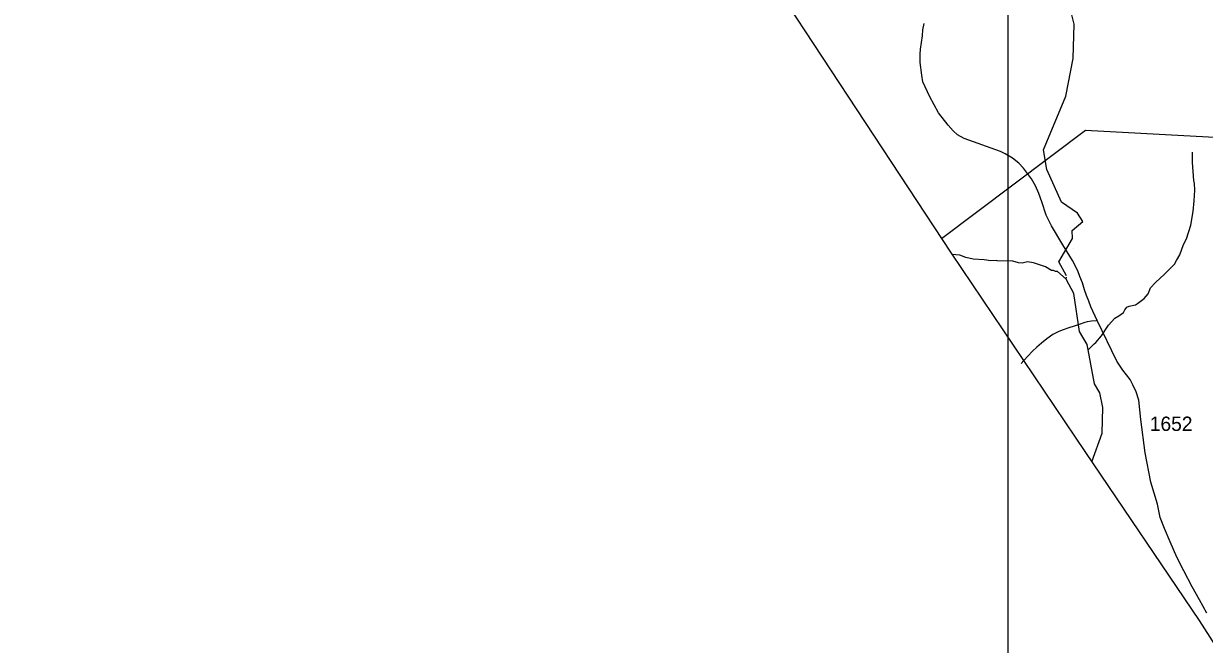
# Model space of a CAD drawing. Extents: x 1268485 to 1426702, y 514839 to 616766.
# Drawn here: x 1268485 to 1280633, y 598258 to 604649 of the extents above; entities that cross this region are included whole.
import ezdxf

# ---------------------------------------------------------------- set-up
doc = ezdxf.new("R2010")
doc.units = 0
for name, color, linetype in [('Old_Level_31', 7, 'Continuous'), ('Old_Level_32', 7, 'Continuous'), ('Old_Level_35', 7, 'Continuous'), ('Old_Level_50', 7, 'Continuous'), ('Old_Level_52', 7, 'Continuous'), ('Old_Level_59', 7, 'Continuous'), ('Old_Level_62', 7, 'Continuous'), ('Old_Level_63', 7, 'Continuous'), ('Old_Level_8', 7, 'Continuous')]:
    doc.layers.add(name, color=color, linetype=linetype)

msp = doc.modelspace()

# ---------------------------------------------------------------- linework, layer by layer
at = {"layer": 'Old_Level_31'}
msp.add_line((1279281.399, 602330.038), (1279281.399, 602330.038), dxfattribs=at)
at = {"layer": 'Old_Level_32'}
msp.add_lwpolyline([(1280657.263, 598578.305), (1280582.342, 598717.072), (1280506.059, 598850.551), (1280420.241, 599017.072), (1280349.406, 599154.517), (1280279.934, 599313.107), (1280221.359, 599450.553), (1280179.131, 599565.53), (1280149.163, 599702.975), (1280083.528, 599927.606), (1280024.873, 600230.577), (1279977.589, 600574.264), (1279959.817, 600773.459), (1279932.574, 600859.362), (1279898.518, 600930.729), (1279868.55, 600986.235), (1279793.629, 601080.067), (1279731, 601174.459), (1279529.362, 601592.843), (1279465.339, 601734.252), (1279443.544, 601792.403), (1279421.749, 601849.231), (1279401.316, 601908.702), (1279378.159, 601981.389), (1279350.915, 602046.147), (1279331.844, 602102.975), (1279275.994, 602210.024), (1279175.191, 602369.936), (1279059.404, 602566.852), (1279004.915, 602675.222), (1278961.325, 602812.668), (1278931.357, 602901.213), (1278895.94, 602979.187), (1278855.074, 603051.874), (1278773.342, 603158.923), (1278724.303, 603211.786), (1278660.279, 603262.007), (1278583.996, 603309.584), (1278534.957, 603332.051), (1278160.353, 603466.852), (1278092.243, 603505.179), (1278047.29, 603544.826), (1277996.889, 603602.976), (1277898.81, 603731.17), (1277807.542, 603893.725), (1277738.071, 604049.672), (1277724.449, 604118.394), (1277708.102, 604247.91), (1277708.102, 604333.813), (1277710.827, 604386.676), (1277732.029, 604522.039), (1277736.709, 604586.236), (1277750.331, 604650.994)], dxfattribs=at)
at = {"layer": 'Old_Level_35'}
msp.add_lwpolyline([(1279521.207, 601590.312), (1279471.174, 601584.315), (1279427.908, 601577.291), (1279402.584, 601570.679), (1279346.093, 601552.378), (1279294.522, 601534.743), (1279238.03, 601516.801), (1279179.078, 601496.86), (1279134.479, 601479.584), (1279072.245, 601448.519), (1279010.525, 601405.15), (1278957.621, 601360.501), (1278907.794, 601316.26), (1278865.45, 601276.07), (1278776.765, 601180.926), (1278746.725, 601150.988)], dxfattribs=at)
at = {"layer": 'Old_Level_50'}
msp.add_lwpolyline([(1281946.81, 605243.25), (1281945.449, 605178.542), (1282185.224, 605012.363), (1282099.59, 603549.992), (1281311.76, 603649.699), (1281243.252, 603450.285), (1279410.691, 603549.992), (1277929.331, 602433.937)], dxfattribs=at)
at = {"layer": 'Old_Level_52'}
msp.add_lwpolyline([(1268485.228, 616765.973), (1271092.371, 612866.089), (1271603.979, 612109.028), (1273440.333, 609310.323), (1274778.27, 607238.2), (1275374.14, 606323.169), (1278026.752, 602285.653), (1279408.707, 600233.543), (1280579.426, 598504.803), (1280995.776, 597856.098), (1281572.617, 596979.448), (1282413.042, 595678.081), (1282806.841, 595082.057), (1283106.06, 594638.413), (1283535.727, 593965.428), (1283962.284, 593326.724), (1284776.514, 592085.916), (1285203.794, 591801.378), (1287417.971, 590296.08), (1292077.678, 587135.953), (1292709.921, 586705.02), (1294394.058, 585547.168), (1295250.323, 584942.843), (1295803.932, 584561.919)], dxfattribs=at)
at = {"layer": 'Old_Level_59'}
for points in [[(1279216.058, 602052.715), (1279136.006, 602197.02), (1279275.031, 602437.136), (1279273.918, 602518.024), (1279384.027, 602611.677), (1279328.048, 602698.158), (1279164.006, 602809.757), (1279012.985, 603147.632), (1278976.999, 603348.583), (1279206.965, 603901.967), (1279283.039, 604291.053), (1279291.959, 604642.052), (1279262.021, 604767.441), (1279279.963, 605190.514), (1279194.046, 605402.282), (1279246.95, 605877.131), (1279274.017, 606625.059), (1279107.002, 606979.594), (1279069.99, 607164.192), (1279036.977, 607628.635)], [(1279473.413, 600137.996), (1279580.057, 600431.512), (1279587.029, 600697.208), (1279556.989, 600848.844), (1279501.009, 600941.835), (1279428.011, 601343.789), (1279348.041, 601479.943), (1279291.036, 601871.695), (1279210.963, 602017.743), (1279213.87, 602037.694)]]:
    msp.add_lwpolyline(points, dxfattribs=at)
at = {"layer": 'Old_Level_62'}
for points in [[(1279437.981, 601288.89), (1279499.093, 601353.337), (1279517.343, 601364.871), (1279575.065, 601433.512), (1279647.756, 601545.778), (1279711.527, 601616.265), (1279752.23, 601639.282), (1279801.033, 601676.089), (1279813.848, 601703.823), (1279836.404, 601731.248), (1279860.703, 601740.629), (1279925.192, 601755.086), (1279945.389, 601766.568), (1280012.851, 601818.959), (1280053.964, 601866.019), (1280077.443, 601927.483), (1280128.808, 601984.231), (1280220.979, 602068.046), (1280325.658, 602173.545), (1280344.523, 602211.07), (1280379.895, 602268.228), (1280418.547, 602375.368), (1280448.074, 602434.679), (1280493.596, 602573.602), (1280516.972, 602713.14), (1280527.737, 602822.945), (1280534.401, 602934.904), (1280532.043, 603002.93), (1280524.969, 603035.123), (1280509.282, 603217.62), (1280509.898, 603323.631)], [(1279210.963, 602017.743), (1279121.355, 602097.355), (1279101.363, 602097.868), (1279081.678, 602108.274), (1279061.48, 602106.788), (1278998.427, 602144.363), (1278875.395, 602185.425), (1278814.432, 602197.646), (1278759.233, 602184.195), (1278719.248, 602187.219), (1278663.782, 602204.597), (1278499.638, 602206.648), (1278493.794, 602210.749), (1278435.661, 602208.186), (1278365.841, 602217.874), (1278255.831, 602222.642), (1278180.269, 602240.532), (1278116.908, 602266.061), (1278036.157, 602271.689)]]:
    msp.add_lwpolyline(points, dxfattribs=at)
at = {"layer": 'Old_Level_63'}
msp.add_line((1278611.149, 616680.45), (1278611.149, 588514.397), dxfattribs=at)

# ---------------------------------------------------------------- texts
at = {"layer": 'Old_Level_8'}
msp.add_text('1652', height=147.6375, dxfattribs=at).set_placement((1280071.336, 600455.443))

doc.saveas('drawing.dxf')
